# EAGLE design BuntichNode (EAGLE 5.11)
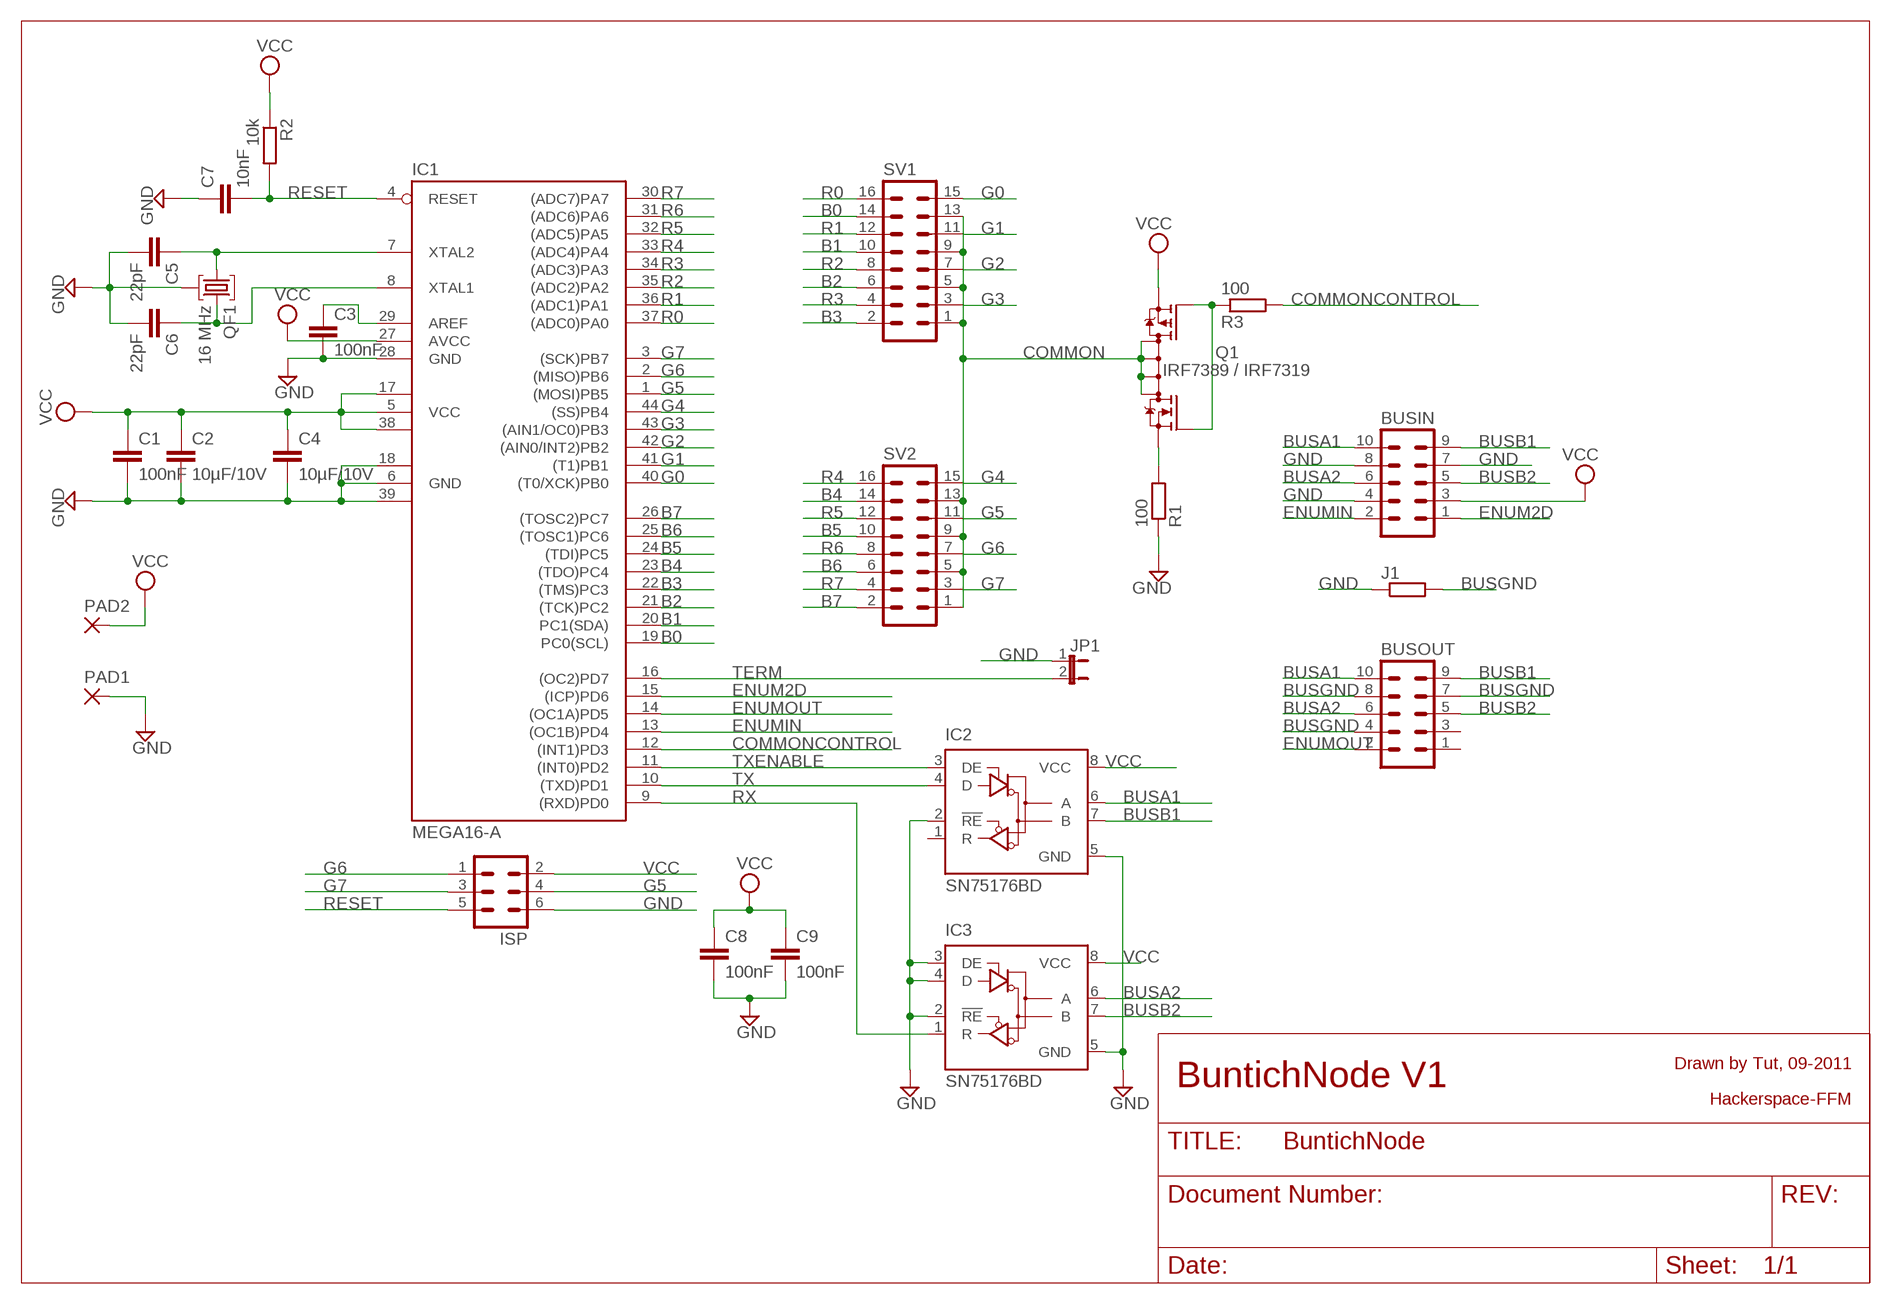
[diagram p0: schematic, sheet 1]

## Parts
BUSIN  ML10  [ML10]
BUSOUT  ML10  [ML10]
C1  100nF  C-EUC0603  [C0603]
C2  10µF/10V  C-EUC1210  [C1210]
C3  100nF  C-EUC0603  [C0603]
C4  10µF/10V  C-EUC1210  [C1210]
C5  22pF  C-EUC0603  [C0603]
C6  22pF  C-EUC0603  [C0603]
C7  10nF  C-EUC0603  [C0603]
C8  100nF  C-EUC0603  [C0603]
C9  100nF  C-EUC0603  [C0603]
IC1  MEGA16-A  [TQFP44]
IC2  SN75176BD  75176AD  [D_R-PDSO-G8]
IC3  SN75176BD  75176AD  [D_R-PDSO-G8]
ISP  ML6  [ML6]
J1  R-EU_R0603  [R0603]
JP1  JP1E  [JP1]
PAD1  3,81/1,4  [3,81/1,4]
PAD2  3,81/1,4  [3,81/1,4]
Q1  IRF7389 / IRF7319  IRF7389  [SO08-IRF]
QF1  16 MHz  8M10AHC49T  [HC49U]
R1  100  R-EU_R0603  [R0603]
R2  10k  R-EU_R0603  [R0603]
R3  100  R-EU_R0603  [R0603]
SV1  ML16  [ML16]
SV2  ML16  [ML16]

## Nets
B0: IC1.19(PC0(SCL)) SV1.14
B1: IC1.20(PC1(SDA)) SV1.10
B2: IC1.21((TCK)PC2) SV1.6
B3: IC1.22((TMS)PC3) SV1.2
B4: IC1.23((TDO)PC4) SV2.14
B5: IC1.24((TDI)PC5) SV2.10
B6: IC1.25((TOSC1)PC6) SV2.6
B7: IC1.26((TOSC2)PC7) SV2.2
BUSA1: BUSIN.10 BUSOUT.10 IC2.6(A)
BUSA2: BUSIN.6 BUSOUT.6 IC3.6(A)
BUSB1: BUSIN.9 BUSOUT.9 IC2.7(B)
BUSB2: BUSIN.5 BUSOUT.5 IC3.7(B)
BUSGND: BUSOUT.4 BUSOUT.7 BUSOUT.8 J1.2
COMMON: Q1.5(D) Q1.6(D) Q1.7(D) Q1.8(D) SV1.1 SV1.5 SV1.9 SV1.13 SV2.1 SV2.5 SV2.9 SV2.13
COMMONCONTROL: IC1.12((INT1)PD3) R3.2
ENUM2D: BUSIN.1 IC1.15((ICP)PD6)
ENUMIN: BUSIN.2 IC1.13((OC1B)PD4)
ENUMOUT: BUSOUT.2 IC1.14((OC1A)PD5)
G0: IC1.40((T0/XCK)PB0) SV1.15
G1: IC1.41((T1)PB1) SV1.11
G2: IC1.42((AIN0/INT2)PB2) SV1.7
G3: IC1.43((AIN1/OC0)PB3) SV1.3
G4: IC1.44((SS)PB4) SV2.15
G5: IC1.1((MOSI)PB5) ISP.4 SV2.11
G6: IC1.2((MISO)PB6) ISP.1 SV2.7
G7: IC1.3((SCK)PB7) ISP.3 SV2.3
GND: BUSIN.4 BUSIN.7 BUSIN.8 C1.2 C2.2 C3.2 C4.2 C5.2 C6.2 C7.1 C8.2 C9.2 IC1.6(GND) IC1.18(GND1) IC1.28(GND) IC1.39(GND2) IC2.2(!RE) IC2.5(GND) IC3.2(!RE) IC3.3(DE) IC3.4(D) IC3.5(GND) ISP.6 J1.1 JP1.1 PAD1.1(P) QF1.2 R1.1
N$1: C5.1 IC1.7(XTAL2) QF1.1
N$2: C6.1 IC1.8(XTAL1) QF1.3
N$3: Q1.1(N-S) R1.2
N$4: Q1.2(N-G) Q1.4(P-G) R3.1
N$5: C3.1 IC1.29(AREF)
R0: IC1.37((ADC0)PA0) SV1.16
R1: IC1.36((ADC1)PA1) SV1.12
R2: IC1.35((ADC2)PA2) SV1.8
R3: IC1.34((ADC3)PA3) SV1.4
R4: IC1.33((ADC4)PA4) SV2.16
R5: IC1.32((ADC5)PA5) SV2.12
R6: IC1.31((ADC6)PA6) SV2.8
R7: IC1.30((ADC7)PA7) SV2.4
RESET: C7.2 IC1.4(RESET) ISP.5 R2.2
RX: IC1.9((RXD)PD0) IC3.1(R)
TERM: IC1.16((OC2)PD7) JP1.2
TX: IC1.10((TXD)PD1) IC2.4(D)
TXENABLE: IC1.11((INT0)PD2) IC2.3(DE)
VCC: BUSIN.3 C1.1 C2.1 C4.1 C8.1 C9.1 IC1.5(VCC) IC1.17(VCC1) IC1.27(AVCC) IC1.38(VCC2) IC2.8(VCC) IC3.8(VCC) ISP.2 PAD2.1(P) Q1.3(P-S) R2.1
Unconnected: BUSOUT.1 BUSOUT.3 IC2.1(R)

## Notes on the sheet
- Drawn by Tut, 09-2011
- BuntichNode V1
- Hackerspace-FFM

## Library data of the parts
BUSIN BUSOUT = con-harting-ml:ML10: HARTING; OC_FARNELL: unknown; OC_NEWARK: unknown
C1 C3 C5-C9 = resistor:C-EU: CAPACITOR, European symbol
C2 C4 = rcl:C-EU: CAPACITOR, European symbol
IC1 = atmel:MEGA16: MICROCONTROLLER 16 Kbytes FLASH 1 kbytes SRAM 512 bytes EEPROM USART 8-channel 10 bit ADC Source: avr.lbr; MPN: ATMEGA16-16AU; OC_FARNELL: 9171134; OC_NEWARK: 96K6515
IC2 IC3 = 751xx:75176A: DIFFERENTIAL BUS TRANSCEIVER Source: http://focus.ti.com/lit/ds/symlink/sn75176a.pdf
ISP = con-harting-ml:ML6: HARTING; OC_FARNELL: unknown; OC_NEWARK: unknown
J1 R1-R3 = resistor:R-EU_: RESISTOR, European symbol
JP1 = jumper:JP1E: JUMPER
PAD1 PAD2 = wirepad:3,81/1,4: THROUGH-HOLE PAD
Q1 = transistor-fet:IRF7389: Complimentary Half Bridge HEXFET Power MOSFET Source: http://www.irf.com/product-info/datasheets/data/irf7389.pdf
QF1 = crystal:8M10AHC49T: Monolithic Crystal Filters Source: www.vanlong.com; OC_FARNELL: unknown; OC_NEWARK: unknown
SV1 SV2 = con-harting-ml:ML16: HARTING; OC_FARNELL: unknown; OC_NEWARK: unknown

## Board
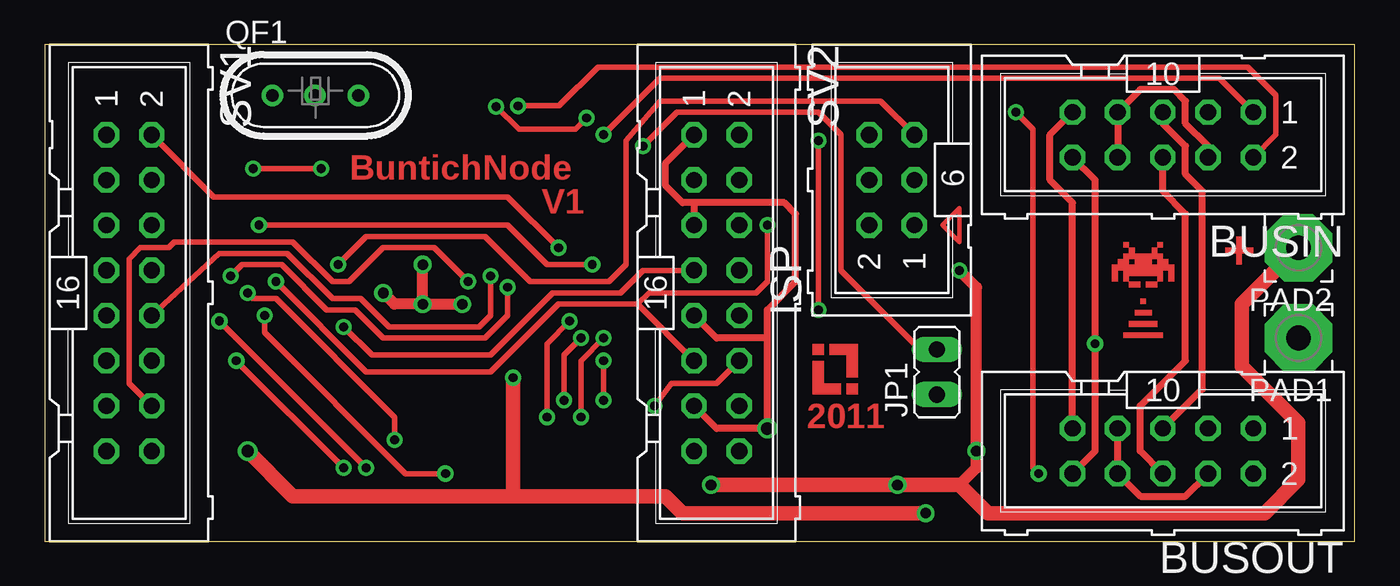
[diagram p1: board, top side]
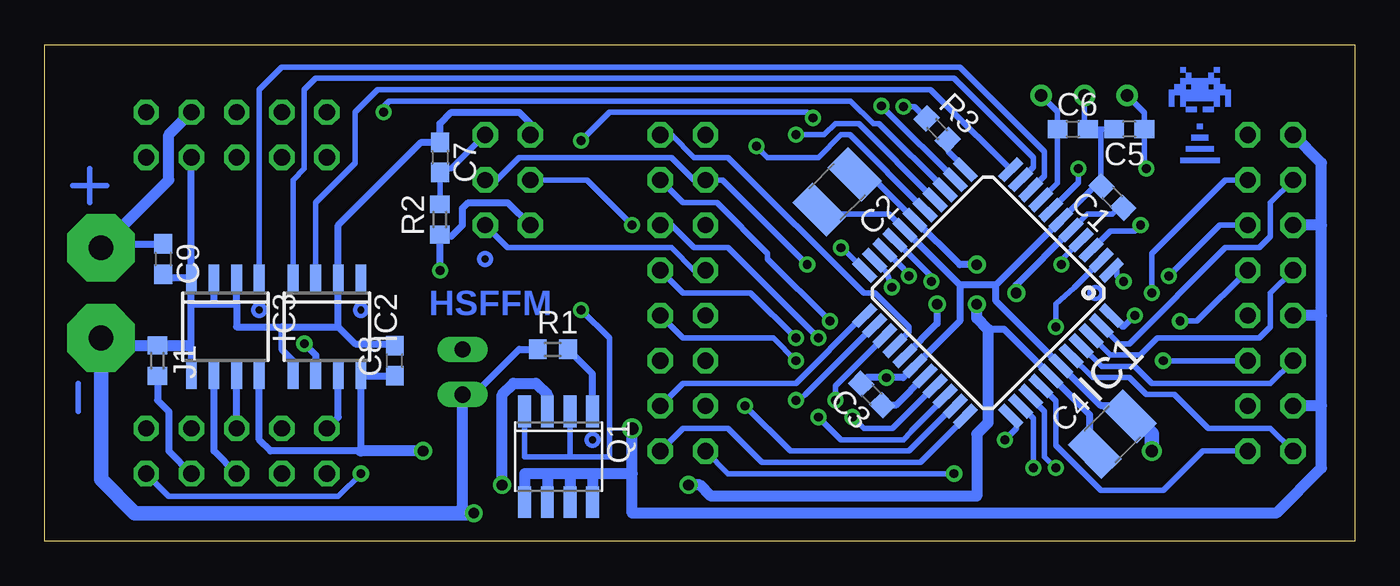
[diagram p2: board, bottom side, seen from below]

Size 73.65 x 27.93 mm. Coordinates in mm from the lower left corner, seen from the top.
Outline: 73.65,27.93 0,27.93 0,0 73.65,0 73.65,27.93
Copper layers (1*16): Top 0.035mm / dielectric 1.5mm / Bottom 0.035mm
Design rules "default *": minimum track width 10mil, minimum drill 0.5mm, track to track 8mil, track to pad 8mil, pad to pad 8mil, via to via 8mil, smd to smd 8mil, copper to edge 40mil, drill to drill 8mil, minimum pad ring 10mil, minimum via ring 8mil, stop-mask expansion 4mil, vias tented up to drill 0mil, thermal gap 10mil

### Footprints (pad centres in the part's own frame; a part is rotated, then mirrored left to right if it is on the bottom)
ML10 = drill 0.914 octagon: 1 -5.08,-1.27; 2 -5.08,1.27; 3 -2.54,-1.27; 4 -2.54,1.27; 5 0,-1.27; 6 0,1.27; 7 2.54,-1.27; 8 2.54,1.27; 9 5.08,-1.27; 10 5.08,1.27
C0603 = smd 1.1 x 1: 1 -0.85,0; 2 0.85,0
C1210 = smd 1.6 x 2.7: 1 -1.4,0; 2 1.4,0
TQFP44 = smd 1.5 x 0.5: 1 -5.8,4; 2 -5.8,3.2; 3 -5.8,2.4; 4 -5.8,1.6; 5 -5.8,0.8; 6 -5.8,0; 7 -5.8,-0.8; 8 -5.8,-1.6; 9 -5.8,-2.4; 10 -5.8,-3.2; 11 -5.8,-4; 23 5.8,-4; 24 5.8,-3.2; 25 5.8,-2.4; 26 5.8,-1.6; 27 5.8,-0.8; 28 5.8,0; 29 5.8,0.8; 30 5.8,1.6; 31 5.8,2.4; 32 5.8,3.2; 33 5.8,4 | smd 0.5 x 1.5: 12 -4,-5.8; 13 -3.2,-5.8; 14 -2.4,-5.8; 15 -1.6,-5.8; 16 -0.8,-5.8; 17 0,-5.8; 18 0.8,-5.8; 19 1.6,-5.8; 20 2.4,-5.8; 21 3.2,-5.8; 22 4,-5.8; 34 4,5.8; 35 3.2,5.8; 36 2.4,5.8; 37 1.6,5.8; 38 0.8,5.8; 39 0,5.8; 40 -0.8,5.8; 41 -1.6,5.8; 42 -2.4,5.8; 43 -3.2,5.8; 44 -4,5.8
D_R-PDSO-G8 = smd 0.6 x 1.5: 1 -1.905,-2.75; 2 -0.635,-2.75; 3 0.635,-2.75; 4 1.905,-2.75; 5 1.905,2.75; 6 0.635,2.75; 7 -0.635,2.75; 8 -1.905,2.75
ML6 = drill 0.914 octagon: 1 -2.54,-1.27; 2 -2.54,1.27; 3 0,-1.27; 4 0,1.27; 5 2.54,-1.27; 6 2.54,1.27
R0603 = smd 1 x 1.1: 1 -0.85,0; 2 0.85,0
JP1 = drill 0.914 long: 1 0,-1.27; 2 0,1.27
3,81/1,4 = drill 1.397 pad 3.81 octagon: 1 0,0
SO08-IRF = smd 0.72 x 1.78: 1 -1.905,-2.543; 2 -0.635,-2.543; 3 0.635,-2.543; 4 1.905,-2.543; 5 1.905,2.543; 6 0.635,2.543; 7 -0.635,2.543; 8 -1.905,2.543
HC49U = drill 0.7 pad 1.2 round: 1 -2.413,0; 2 -0.027,0; 3 2.413,0
ML16 = drill 0.914 octagon: 1 -8.89,-1.27; 2 -8.89,1.27; 3 -6.35,-1.27; 4 -6.35,1.27; 5 -3.81,-1.27; 6 -3.81,1.27; 7 -1.27,-1.27; 8 -1.27,1.27; 9 1.27,-1.27; 10 1.27,1.27; 11 3.81,-1.27; 12 3.81,1.27; 13 6.35,-1.27; 14 6.35,1.27; 15 8.89,-1.27; 16 8.89,1.27

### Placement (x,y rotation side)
BUSIN  62.85,22.85 180 top
BUSOUT  62.85,5.07 180 top
C1  13.64,19.36 135 bottom
C2  29.1,19.64 225 bottom
C3  27.16,8.25 135 bottom
C4  13.64,6.02 45 bottom
C5  12.69,23.17 180 bottom
C6  15.86,23.17 0 bottom
C7  51.42,21.58 270 bottom
C8  53.96,10.15 90 bottom
C9  66.98,15.87 270 bottom
IC1  20.62,13.96 225 bottom
IC2  57.77,12.05 180 bottom
IC3  63.49,12.05 180 bottom
ISP  47.61,20.31 90 top
J1  67.3,10.15 270 bottom
JP1  50.15,9.52 0 top
PAD1  70.47,11.42 180 top
PAD2  70.47,16.5 180 top
Q1  44.75,4.75 180 bottom
QF1  15.23,25.07 0 top
R1  45.07,10.79 0 bottom
R2  51.42,18.09 90 bottom
R3  23.48,23.17 315 bottom
SV1  4.75,13.96 270 top
SV2  37.77,13.96 270 top

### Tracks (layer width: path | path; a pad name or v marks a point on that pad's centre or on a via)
B0  (via drill 0.5)
  Top 0.305: v23.8,14.6 21.89,16.5 19.04,16.5 17.13,14.6 16.18,14.6 13.96,16.82 7.29,16.82 6.97,16.5 5.38,16.5 4.75,15.87 4.75,8.88 SV1.14
  Bottom 0.305: IC1.19 23.8,14.87 v23.8,14.6
B1  (via drill 0.5)
  Top 0.305: SV1.10 9.83,16.18 13.64,16.18 16.18,13.64 17.77,13.64 19.35,12.05 24.44,12.05 25.07,12.69 v25.07,14.91
  Bottom 0.305: IC1.20 25.39,15.33 v25.07,14.91
B2  (via drill 0.5)
  Top 0.305: v10.46,14.91 11.1,15.55 13.32,15.55 15.86,13.01 17.45,13.01 19.04,11.42 24.75,11.42 26.02,12.69 v26.02,14.28
  Bottom 0.305: SV1.6 7.61,17.77 v10.46,14.91 | IC1.21 26.34,15.15 v26.02,14.28
B3  (via drill 0.5)
  Top 0.305: v28.88,16.5 arc90 v28.88,16.5 26.02,19.36 9.51,19.36 SV1.2
  Bottom 0.305: v28.88,16.5 28.5,16.18 IC1.22
B4
  Bottom 0.305: IC1.23 27.61,12.69 31.42,8.88 37.77,8.88 SV2.14
B5  (via drill 0.5)
  Top 0.305: v31.42,7.93 v31.42,10.15
  Bottom 0.305: IC1.24 27.01,12.12 30.87,8.26 31.19,8.01 v31.42,7.93 | v31.42,10.15 32.69,11.42 37.77,11.42 SV2.10
B6  (via drill 0.5)
  Top 0.305: v29.2,7.93 29.2,10.47 v30.15,11.42
  Bottom 0.305: IC1.25 26.42,11.51 29.2,8.73 v29.2,7.93 | v30.15,11.42 35.23,16.5 37.14,16.5 38.4,17.77 SV2.6
B7
  Bottom 0.305: 25.86,10.87 IC1.26 25.07,11.78 25.07,12.05 26.98,13.96 27.61,13.96 35.23,21.58 37.14,21.58 38.4,22.85 SV2.2
BUSA1  (via drill 0.5)
  Top 0.406: BUSOUT.10 59.04,5.07 v59.04,11.1 59.04,20.31 BUSIN.10
  Bottom 0.406: IC2.6 58.41,10.47 v59.04,11.1
BUSA2
  Top 0.406: BUSIN.6 62.85,19.67 64.12,18.4 64.12,10.15 61.58,7.61 61.58,5.07 BUSOUT.6
  Bottom 0.406: IC3.6 64.12,5.07 BUSOUT.6
BUSB1
  Top 0.406: BUSOUT.9 57.77,19.04 56.5,20.31 56.5,22.85 BUSIN.9
  Bottom 0.406: IC2.7 57.14,6.98 BUSOUT.9
BUSB2
  Top 0.406: BUSOUT.5 65.08,8.56 65.08,19.67 64.12,20.63 64.12,22.21 62.85,23.48 BUSIN.5
  Bottom 0.406: BUSOUT.5 IC3.7
BUSGND
  Top 0.406: BUSOUT.7 BUSOUT.8 61.58,2.53 64.12,2.53 BUSOUT.4
  Bottom 0.406: J1.2 67.3,7.93 66.66,7.29 66.66,5.07 BUSOUT.4
COMMON  (via drill 0.7)
  Top 0.406: SV2.13 37.77,6.34 v40.63,6.34 40.63,11.42 | SV2.9 37.77,11.42 40.63,11.42 | 40.63,11.42 40.63,13.01 42.21,14.6 42.21,18.4 41.58,19.04 36.5,19.04 | 36.5,19.04 SV2.5 | 36.5,19.04 35.86,19.04 34.91,19.99 34.91,21.26 SV2.1
  Bottom 0.61: 40.63,3.8 40.63,1.58 4.43,1.58 1.89,4.12 1.89,7.61 | 40.63,3.8 v40.63,6.34 | Q1.5 46.66,3.8 45.39,3.8 | 40.63,3.8 42.85,3.8 | 42.85,3.8 44.12,3.8 | 44.12,3.8 45.39,3.8 | 42.85,3.8 Q1.8 | 44.12,3.8 Q1.7 | 45.39,3.8 Q1.6 | 1.89,7.61 1.89,12.69 | 1.89,12.69 1.89,17.77 | 1.89,17.77 1.89,21.26 SV1.1 | 1.89,17.77 SV1.5 | 1.89,12.69 SV1.9 | 1.89,7.61 SV1.13
COMMONCONTROL
  Bottom 0.305: IC1.12 21.9,20.95 22.85,21.9 22.85,22.53 R3.2
ENUM2D  (via drill 0.5)
  Top 0.305: BUSIN.1 66.03,26.02 34.6,26.02 v31.42,22.85
  Bottom 0.305: IC1.15 27.89,23.48 29.2,23.48 29.83,22.85 v31.42,22.85
ENUMIN  (via drill 0.5)
  Top 0.305: BUSIN.2 69.2,22.85 69.2,25.07 67.61,26.66 31.1,26.66 28.92,24.48 v26.62,24.48
  Bottom 0.305: IC1.13 26.3,24.16 v26.62,24.48
ENUMOUT  (via drill 0.5)
  Top 0.305: v54.6,24.12 55.55,23.17 55.55,4.12 v55.87,3.8
  Bottom 0.305: BUSOUT.2 66.66,2.53 57.14,2.53 v55.87,3.8 | IC1.14 26.76,23.48 27.07,23.48 28.34,24.75 54.28,24.75 54.6,24.44 v54.6,24.12
G0
  Bottom 0.305: SV1.15 4.75,6.34 8.24,6.34 10.15,8.25 11.74,8.25 12.69,9.2 14.73,9.2 IC1.40
G1
  Bottom 0.305: SV1.11 4.75,8.88 11.42,8.88 12.37,9.83 14.23,9.83 IC1.41
G2
  Bottom 0.305: IC1.42 13.74,10.47 12.05,10.47 11.1,11.42 5.38,11.42 4.75,12.05 4.75,13.96 SV1.7
G3
  Bottom 0.305: IC1.43 13.24,11.1 12.69,11.1 7.29,16.5 5.38,16.5 4.75,17.13 4.75,19.04 SV1.3
G4  (via drill 0.5)
  Top 0.305: v12.37,12.69 12.37,11.74 20.31,3.8 v22.53,3.8
  Bottom 0.305: IC1.44 13.06,12.05 13.01,12.05 v12.37,12.69 | v22.53,3.8 35.23,3.8 SV2.15
G5  (via drill 0.5)
  Top 0.305: v13.01,14.6 18.09,9.52 25.07,9.52 28.88,13.33 33.32,13.33 | 33.32,13.33 SV2.11 | v40.63,17.77 40.63,14.6 39.99,13.96 33.96,13.96 33.32,13.33
  Bottom 0.305: v13.01,14.6 13.37,14.91 13.37,15.23 IC1.1 | v40.63,17.77 43.17,20.31 ISP.4
G6  (via drill 0.5)
  Top 0.305: v16.82,12.05 18.4,10.47 25.07,10.47 28.56,13.96 32.37,13.96 33.64,15.23 SV2.7
  Bottom 0.305: IC1.2 15.78,14.28 16.82,13.33 v16.82,12.05 | SV2.7 37.14,15.23 38.4,16.5 47.61,16.5 ISP.1
G7  (via drill 0.5)
  Top 0.305: v12.05,17.77 26.02,17.77 28.25,15.55 v30.78,15.55
  Bottom 0.305: IC1.3 13.74,17.45 12.37,17.45 v12.05,17.77 | v30.78,15.55 35.55,20.31 SV2.3 37.14,20.31 38.4,21.58 46.98,21.58 48.25,20.31 ISP.3
GND  (via drill 0.5, 0.6, 0.7)
  Top 0.406: BUSIN.8 BUSIN.7 61.58,25.39 63.49,25.39 64.12,24.75 64.12,23.48 65.39,22.21 BUSIN.4
  Top 0.813: v11.42,5.07 13.96,2.53 26.34,2.53 | 26.34,2.53 34.91,2.53 35.86,1.58 v49.52,1.58 | v26.34,9.2 26.34,2.53
  Bottom 0.305: IC1.6 14.43,20.15 | 14.43,20.15 14.27,20.31 14.27,23.17 | 14.27,23.17 C6.2 15.2,23.36 QF1.2 | 14.27,23.17 C5.2 | 14.43,20.15 C1.2 | IC1.18 26.2,18.4 29.83,18.4 30.07,18.65 C2.2 | C8.2 53.86,11.1 | PAD1.1 70.69,11
  Bottom 0.406: 65.39,13.33 IC3.4 | 65.39,10.79 65.39,13.33 | 65.39,10.79 IC3.5 | 62.85,13.33 IC3.2 | 65.39,13.33 64.12,13.33 | 64.12,13.33 IC3.3 | 64.12,13.33 62.85,13.33 | 65.61,11 65.39,10.79 | 60.31,12.05 62.85,12.05 62.85,13.33 | 60.31,12.05 57.14,12.05 | 57.14,12.05 56.18,11.1 54.07,11.1 C8.2 | 57.14,12.05 IC2.2 57.14,17.77 52.48,22.43 C7.1 51.42,23.48 50.79,24.12 46.98,24.12 46.34,23.48 ISP.6 | 22.21,14.42 IC1.18 | 22.21,14.42 22.21,12.37 IC1.28 25.39,9.2 v26.34,9.2 27.44,9.2 C3.2 | 20.17,14.42 IC1.6 | 20.17,14.42 22.21,14.42 | 20.17,14.42 20.17,13.5 IC1.39 14.28,7.61 13.32,7.61 12.72,7.01 C4.2 | IC3.4 BUSIN.4 | IC3.4 66.77,14.8 arc90 C9.2 | R1.1 46.98,10.79 49.2,8.56 49.83,8.56 JP1.1 | IC2.5 59.68,10.15 60.31,10.79 60.31,12.05
  Bottom 0.61: 65.61,11 J1.1 70.05,11 arc90 PAD1.1 | JP1.1 50.15,1.9 50.47,1.58
  Bottom 0.813: v11.42,5.07 11.42,6.02 12.37,6.98 12.69,6.98 | PAD1.1 70.47,3.48 68.57,1.58 50.47,1.58 v49.52,1.58
N$1  (via drill 0.5)
  Top 0.305: v11.74,20.94 v15.54,20.94
  Bottom 0.305: IC1.7 15.54,20.17 v15.54,20.94 | v11.74,20.94 11.84,21.05 C5.1 11.84,24.09 QF1.1
N$2
  Bottom 0.305: QF1.3 16.71,24.14 C6.1 16.71,20.13 IC1.8
N$3
  Bottom 0.406: Q1.1 42.85,9.41 R1.2
N$4  (via drill 0.5)
  Top 0.305: v43.49,13.01 v43.49,22.53 | v30.47,23.8 29.83,23.17 26.66,23.17 v25.39,24.44
  Bottom 0.305: 44.12,4.75 Q1.2 | 44.12,4.75 41.9,4.75 41.9,11.42 v43.49,13.01 | Q1.4 46.66,4.75 44.12,4.75 | v43.49,22.53 41.9,24.12 30.78,24.12 v30.47,23.8 | v25.39,24.44 24.75,24.44 R3.1
N$5
  Bottom 0.406: IC1.29 25.81,7.64 C3.1
N$6
  Bottom 0.305: 71.74,7.29 71.74,8.88
N$7
  Bottom 0.305: 71.11,19.04 71.11,20.94
N$8
  Bottom 0.305: 70.16,19.99 72.06,19.99
N$10
  Top 0.254: 50.47,17.77 51.42,16.82 51.42,18.72 50.47,17.77
R0
  Bottom 0.305: SV1.16 8.56,5.07 10.78,2.85 14.27,2.85 16.82,5.39 16.82,7.89 IC1.37
R1  (via drill 0.5)
  Top 0.305: v10.78,10.15 v16.82,4.12
  Bottom 0.305: SV1.12 v10.78,10.15 | IC1.36 18.22,8.06 17.45,7.29 17.45,4.75 v16.82,4.12
R2  (via drill 0.5)
  Top 0.305: v9.83,12.37 v18.09,4.12
  Bottom 0.305: SV1.8 8.88,12.37 v9.83,12.37 | IC1.35 18.09,6.9 v18.09,4.12
R3  (via drill 0.5)
  Top 0.305: v19.67,5.71 19.67,6.98 13.01,13.64 11.74,13.64 v11.42,13.96
  Bottom 0.305: SV1.4 7.29,20.31 11.42,16.18 v11.42,13.96 | IC1.34 19.04,6.72 19.04,6.34 v19.67,5.71
R4
  Bottom 0.305: IC1.33 21.9,6.97 24.44,4.44 33.32,4.44 35.23,6.34 37.77,6.34 SV2.16
R5  (via drill 0.5)
  Top 0.305: SV2.12 37.77,8.88 35.23,8.88 v34.28,7.61
  Bottom 0.305: IC1.32 22.54,7.6 25.07,5.07 31.74,5.07 v34.28,7.61
R6  (via drill 0.5)
  Top 0.305: v31.42,11.42 30.15,10.15 v30.15,6.98
  Bottom 0.305: IC1.31 23.03,8.1 24.93,6.2 24.93,6.16 25.39,5.71 28.88,5.71 v30.15,6.98 | SV2.8 37.77,13.96 33.96,13.96 v31.42,11.42
R7  (via drill 0.5)
  Top 0.305: v29.51,12.37 28.25,11.1 v28.25,6.98
  Bottom 0.305: IC1.30 25.99,6.34 27.61,6.34 v28.25,6.98 | SV2.4 37.77,19.04 35.86,19.04 33.01,16.18 33.01,15.87 v29.51,12.37
RESET  (via drill 0.5)
  Top 0.305: v16.5,15.55 18.09,17.13 24.75,17.13 27.29,14.6 31.74,14.6 32.69,15.55 32.69,22.53 34.6,24.75 46.98,24.75 ISP.5
  Bottom 0.305: IC1.4 16.46,15.87 v16.5,15.55 | R2.2 C7.2 51.21,20.94 50.79,20.94 ISP.5
RX
  Bottom 0.305: IC1.9 17.45,20.53 17.45,21.9 22.21,26.66 60.31,26.66 61.58,25.39 IC3.1
TERM  (via drill 0.5)
  Top 0.305: v33.64,22.21 35.55,24.12 43.49,24.12 44.75,22.85 44.75,15.23 49.2,10.79 JP1.2
  Bottom 0.305: IC1.16 28.38,22.85 28.88,22.85 30.15,21.58 33.01,21.58 v33.64,22.21
TX
  Bottom 0.305: IC1.10 18.09,21.02 18.09,21.58 22.53,26.02 58.41,26.02 59.04,25.39 59.04,20.94 59.68,20.31 IC2.4
TXENABLE
  Bottom 0.305: IC1.11 23.16,24.7 23.86,25.39 54.92,25.39 56.18,24.12 56.18,21.26 58.41,19.04 IC2.3
VCC  (via drill 0.5, 0.6)
  Top 0.61: v19.04,13.96 19.67,13.33 v21.26,13.33 | v21.26,13.33 v21.26,15.55 | v21.26,13.33 v23.48,13.33 | 51.42,3.17 52.38,4.12 v52.38,5.07 52.38,14.28 v51.42,15.23
  Top 0.813: PAD2.1 67.3,13.33 67.3,9.83 70.47,6.66 70.47,3.48 68.57,1.58 53.01,1.58 51.42,3.17 v47.93,3.17 v37.45,3.17
  Bottom 0.305: IC1.5 15.05,18.4 13.64,18.4 13.29,18.76 C1.1 | IC1.17 27.29,20.63 C2.1 | 50.79,17.13 51.32,17.13 R2.1
  Bottom 0.406: IC3.8 61.58,5.71 60.95,5.07 55.87,5.07 IC2.8 C8.1 | IC1.5 19.04,14.42 v19.04,13.96 | IC1.17 22.21,15.55 v21.26,15.55 | IC1.27 23.48,12.23 v23.48,13.33 | C4.1 14.63,5.11 14.91,5.39 14.91,7.11 IC1.38 19.6,11.81 19.71,11.92 20.62,11.92 | 50.79,17.13 50.15,17.77 50.15,18.72 49.83,19.04 47.61,19.04 ISP.2 | v51.42,15.23 R2.1 | C9.1 70.26,16.71 arc-90 PAD2.1
  Bottom 0.61: v37.45,3.17 36.82,3.17 36.18,2.53 21.26,2.53 21.26,6.02 20.62,6.66 20.62,11.92 21.26,12.55 v21.26,13.33 | Q1.3 45.39,8.25 46.03,8.88 47.29,8.88 47.93,8.25 v47.93,3.17 | v52.38,5.07 55.87,5.07 | BUSIN.3 66.66,22.85 66.66,20.31 PAD2.1
(copper drawn outside any net)
  shapes: Bottom area x19, Bottom circle x5, Top area x28

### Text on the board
Top: BuntichNode | V1 | 2011
Bottom: HSFFM
tStop: BuntichNode | V1 | 2011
